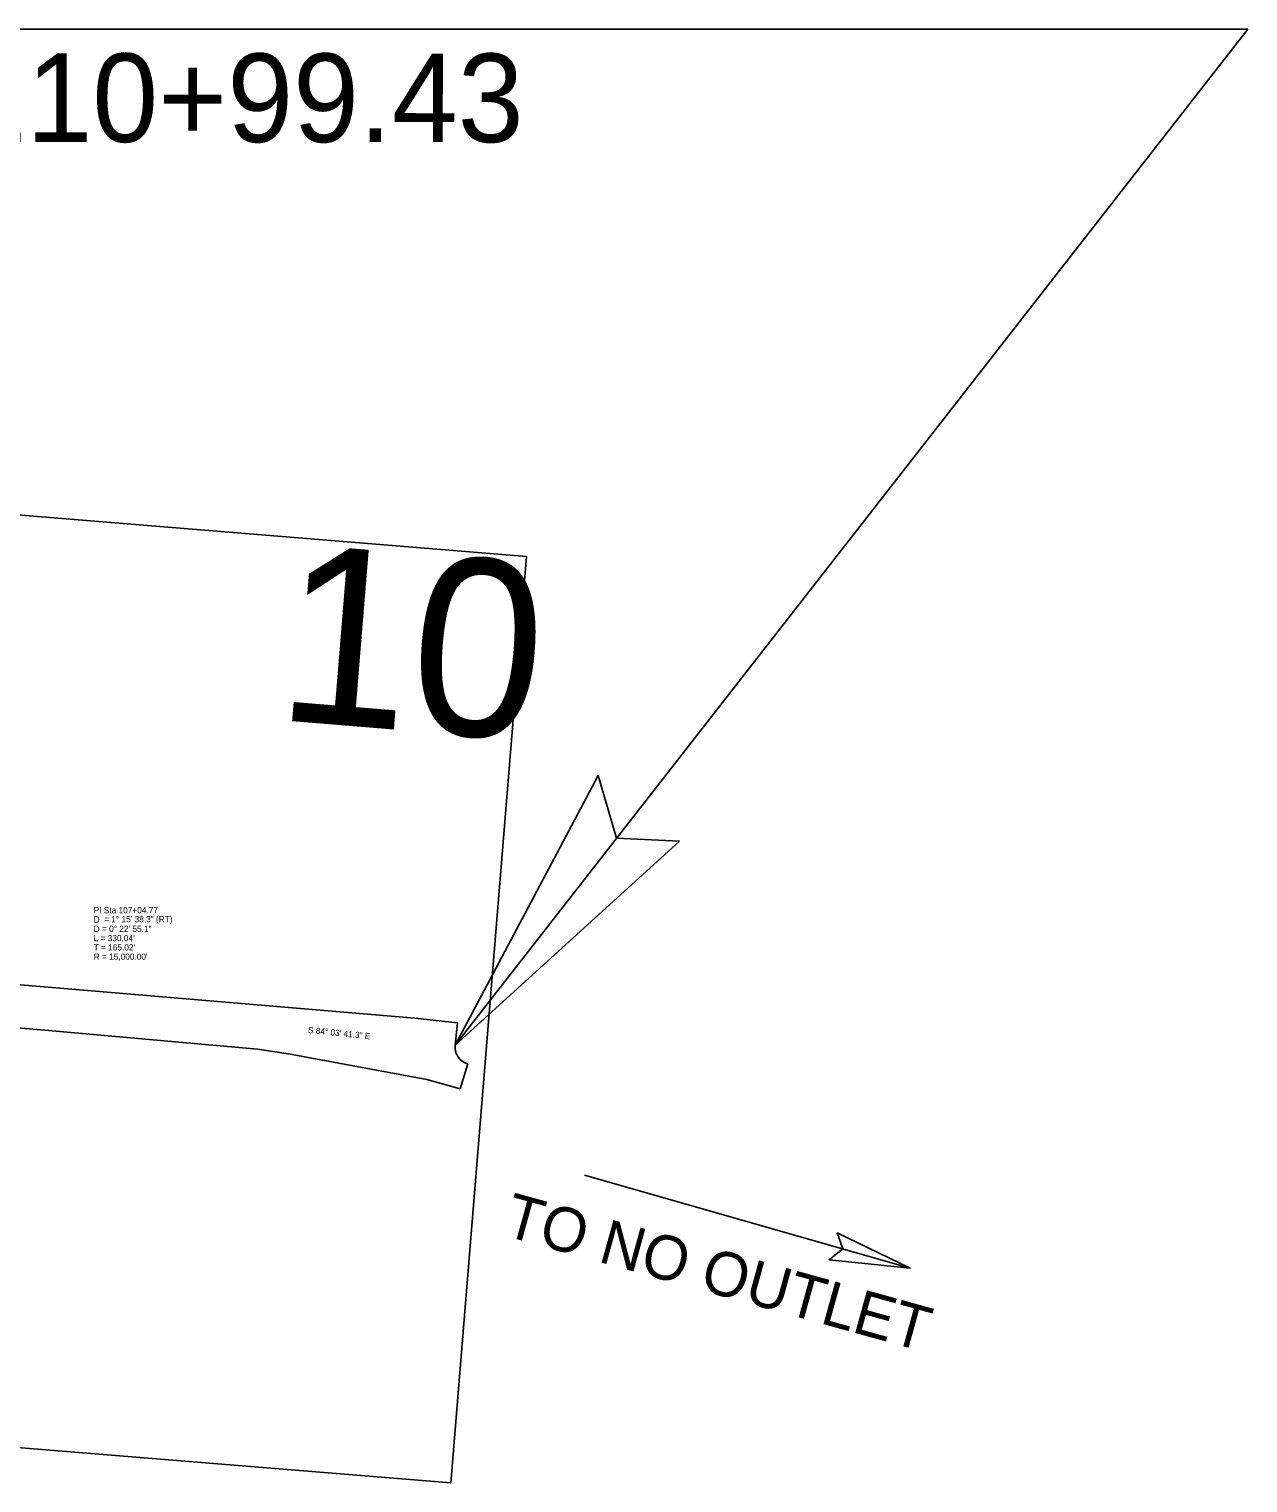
# Model space of a CAD drawing. Extents: x 925297 to 940193, y 663541 to 689899.
# Drawn here: x 936830 to 938207, y 683818 to 685461 of the extents above; entities that cross this region are included whole.
import ezdxf

# ---------------------------------------------------------------- set-up
doc = ezdxf.new("R2010")
doc.units = 0
for name, color, linetype in [('Default', 7, 'Continuous'), ('Exist Horizontal Alignment Curve and Spiral Data', 7, 'Continuous'), ('Exist Horizontal Alignment Direction Label', 7, 'Continuous'), ('Exist Horizontal Alignment Tick Large', 7, 'Continuous'), ('Prop DSN Text', 7, 'Continuous'), ('Prop Shade Light', 7, 'Continuous'), ('Prop Terminator CELL', 7, 'Continuous'), ('Sheet Title CELL', 7, 'Continuous')]:
    doc.layers.add(name, color=color, linetype=linetype)

# ---------------------------------------------------------------- blocks, each defined once
blk = doc.blocks.new('Terminator')
at = {"layer": 'Prop Terminator CELL'}
blk.add_lwpolyline([(-9, 1.55), (0, 0), (-9.05, -1.6), (-7.9, 0)], close=True, dxfattribs=at)

msp = doc.modelspace()

# ---------------------------------------------------------------- linework, layer by layer
at = {"layer": 'Default'}
for p, q in [((937391.9, 684865), (935896.8, 684987.3)), ((937306.2, 683818.5), (937391.9, 684865)), ((935811.2, 683940.8), (937306.2, 683818.5))]:
    msp.add_line(p, q, dxfattribs=at)
at = {"layer": 'Exist Horizontal Alignment Tick Large'}
for p, q in [((936165.7, 685461), (938206.6, 685461)), ((938206.6, 685461), (937311.3, 684313.1)), ((937457.3, 684166.3), (937825, 684061.2))]:
    msp.add_line(p, q, dxfattribs=at)
at = {"layer": 'Prop Shade Light'}
for p, q in [((936457.4, 684411.9), (937265.8, 684343.4)), ((936847.8, 684329.9), (936812.4, 684333.1)), ((937088.2, 684308.5), (936847.8, 684329.9)), ((937265.8, 684343.4), (937314, 684338.3)), ((937314, 684338.3), (937311.3, 684313.1)), ((937123, 684303.2), (937088.2, 684308.5)), ((937279.3, 684274.2), (937123, 684303.2)), ((937325.4, 684291.9), (937316.9, 684263.8)), ((937316.9, 684263.8), (937279.3, 684274.2))]:
    msp.add_line(p, q, dxfattribs=at)
msp.add_arc((937331.1, 684311), 19.9, 174.0254, 253.2659, dxfattribs=at)

# ---------------------------------------------------------------- block references
at = {"layer": 'Exist Horizontal Alignment Tick Large', "xscale": 9.999999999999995, "yscale": 9.999999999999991, "rotation": -15.941056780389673}
msp.add_blockref('Terminator', (937825, 684061.2), dxfattribs=at)
at = {"layer": 'Sheet Title CELL', "xscale": 37.50000000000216, "yscale": 37.50000000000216, "rotation": -127.95082910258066}
msp.add_blockref('Terminator', (937311.3, 684313.1), dxfattribs=at)

# ---------------------------------------------------------------- texts
at = {"layer": 'Default'}
msp.add_text('TO NO OUTLET', height=50, rotation=344.5068, dxfattribs=at).set_placement((937364, 684098.5))
at = {"layer": 'Exist Horizontal Alignment Curve and Spiral Data'}
for s, p in [('PI Sta 107+04.77', (936903, 684462)), ('D', (936903, 684451.5)), ('= 1%%d 15\' 38.3" (RT)', (936914.8, 684451.9)), ('D = 0%%d 22\' 55.1"', (936903, 684441)), ("T = 165.02'", (936903, 684420)), ("L = 330.04'", (936903, 684430.5)), ("R = 15,000.00'", (936903, 684409.5))]:
    msp.add_text(s, height=7, dxfattribs=at).set_placement(p)
at = {"layer": 'Exist Horizontal Alignment Direction Label'}
msp.add_text('S 84%%d 03\' 41.3" E', height=7, rotation=354.0615, dxfattribs=at).set_placement((937144.7, 684326.9))
at = {"layer": 'Exist Horizontal Alignment Tick Large'}
msp.add_text('-EL- STA 110+99.43', height=100, rotation=359.9706, dxfattribs=at).set_placement((936165.7, 685333.8))
at = {"layer": 'Prop DSN Text'}
msp.add_text('10', height=200, rotation=355.3231, dxfattribs=at).set_placement((937106.8, 684680.7))

doc.saveas('drawing.dxf')
